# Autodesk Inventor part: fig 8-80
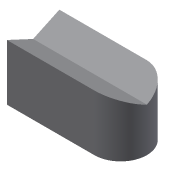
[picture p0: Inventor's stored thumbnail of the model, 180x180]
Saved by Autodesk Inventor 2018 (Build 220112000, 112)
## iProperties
Created: 2011-07
Part Number: fig 8-80
Material: Generic
Document SubType Name: Modeling
Designer: CadCim
Density: 1 g/cm^3
Appearance: Default
Author: CadCim
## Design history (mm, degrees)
sketch "Sketch1"
  geometry: L1 (-16, 5)-(-16, -7); L2 (-16, -7)-(4, -7); L3 (4, 5)-(-16, 5); A1 r 6 centre (4, -1) between (4, -7) and (4, 5); 1 further point
  constraints: 6 end point, 2 point on circle, 2 tangent, 1 centre point, 1 parallel, 1 perpendicular, 1 vertical
extrude "Extrusion1" new body sketch "Sketch1" distance "d0" = 10; taper "d1" = 0 deg
sketch "Sketch2"
  geometry: L1 (-16, -1)-(10, -1); 1 further point
  constraints: 2 end point, 1 horizontal
feature "FaceDraft1" sketch "Sketch2" dims angle "d2" = -25 deg
body "Solid1"
